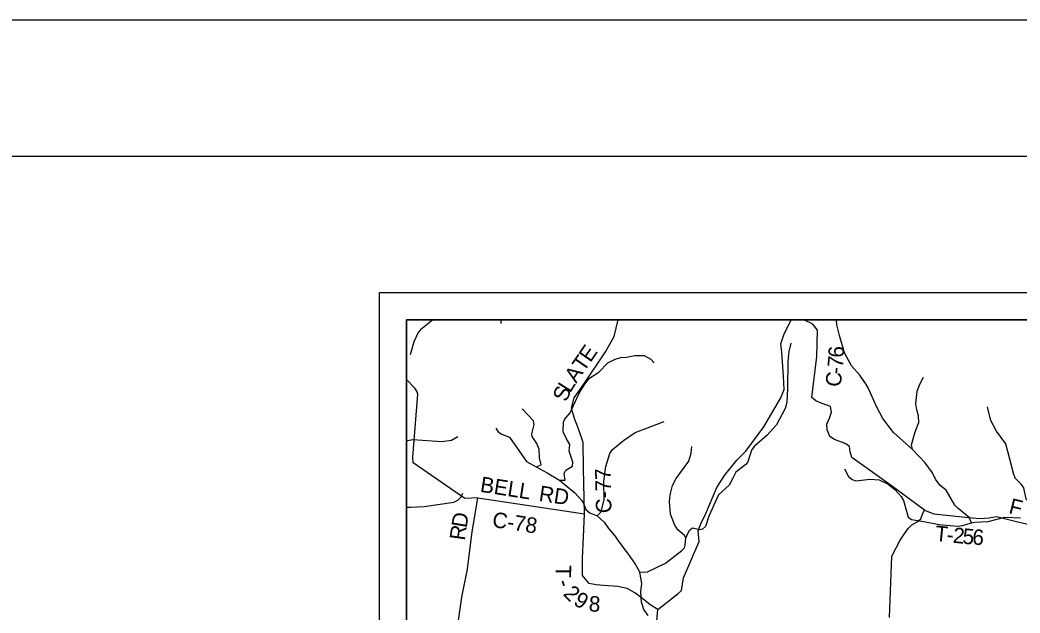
# Model space of a CAD drawing. Extents: x 0 to 34, y 0 to 22.
# Drawn here: x 22.598 to 26.267, y 19.825 to 22 of the extents above; entities that cross this region are included whole.
import ezdxf

# ---------------------------------------------------------------- set-up
doc = ezdxf.new("R2010")
doc.units = 0
for name, color, linetype in [('GM_X_County', 7, 'Continuous'), ('GM_X_County_Road', 7, 'Continuous'), ('GM_X_County_Road_Text', 7, 'Continuous'), ('GM_X_Minor_River', 7, 'Continuous'), ('GM_X_Township', 7, 'Continuous'), ('GM_X_Township_Road', 7, 'Continuous'), ('GM_X_Township_Road_Text', 7, 'Continuous'), ('SH_Border', 7, 'Continuous'), ('SH_Cut_Line', 7, 'Continuous'), ('SH_Data', 7, 'Continuous')]:
    doc.layers.add(name, color=color, linetype=linetype)

msp = doc.modelspace()

# ---------------------------------------------------------------- linework, layer by layer
at = {"layer": 'GM_X_County'}
msp.add_lwpolyline([(29.025, 20.9), (24.0167, 20.9), (24.0167, 14.5214)], dxfattribs=at)
at = {"layer": 'GM_X_County_Road'}
for points in [[(24.669, 20.1887), (24.6651, 20.3561), (24.6643, 20.4497), (24.6473, 20.5002), (24.6327, 20.5382), (24.621, 20.5761), (24.6315, 20.6146), (24.6688, 20.6673), (24.7466, 20.7829), (24.7779, 20.8392), (24.7928, 20.9)], [(25.7887, 19.8078), (25.7968, 20.0331), (25.8276, 20.0915), (25.8371, 20.1069), (25.8571, 20.1345), (25.8703, 20.1486), (25.8899, 20.1588), (25.9031, 20.1703), (25.9108, 20.191), (25.9168, 20.2026), (25.8038, 20.2848), (25.6505, 20.3956), (25.6434, 20.4163), (25.6412, 20.4357), (25.6282, 20.4459), (25.5868, 20.4609), (25.5693, 20.4724), (25.5596, 20.4965), (25.5586, 20.5175), (25.5682, 20.5393), (25.5752, 20.5611), (25.5711, 20.5822), (25.541, 20.5935), (25.5181, 20.6028), (25.5036, 20.6149), (25.522, 20.7657), (25.5235, 20.8619), (25.5063, 20.8847), (25.4744, 20.9)], [(24.1402, 19.4296), (24.1499, 19.4856), (24.1526, 19.5395), (24.1535, 19.5824), (24.1536, 19.6147), (24.16, 19.6322), (24.177, 19.6456), (24.1928, 19.6635), (24.194, 19.7022), (24.219, 19.8827), (24.2396, 19.9857), (24.2555, 20.1141), (24.2778, 20.2475), (24.2307, 20.2449), (24.0407, 20.3755), (24.0393, 20.3964), (24.0579, 20.6277), (24.0544, 20.6389), (24.0468, 20.649), (24.0167, 20.6817)], [(24.2778, 20.2475), (24.669, 20.1887)]]:
    msp.add_lwpolyline(points, dxfattribs=at)
at = {"layer": 'GM_X_Minor_River'}
for points in [[(24.1123, 20.9), (24.0677, 20.8641), (24.0591, 20.8543), (24.0429, 20.8193), (24.0302, 20.772)], [(24.3621, 20.9), (24.3624, 20.8869)], [(26.0887, 20.1557), (26.0799, 20.1757), (26.0395, 20.2083), (26.028, 20.221), (25.9956, 20.276), (25.9743, 20.2927), (25.9573, 20.3158), (25.9459, 20.3384), (25.9193, 20.3757), (25.872, 20.4248), (25.8022, 20.4869), (25.7633, 20.5377), (25.7416, 20.5795), (25.7092, 20.6534), (25.7015, 20.665), (25.6956, 20.6746), (25.6789, 20.6977), (25.6488, 20.7313), (25.6235, 20.7796), (25.6046, 20.8426), (25.5955, 20.8819), (25.5939, 20.9)], [(25.4256, 20.8143), (25.4186, 20.7836), (25.4149, 20.7472), (25.4134, 20.6481), (25.4117, 20.5968), (25.4048, 20.5749), (25.3741, 20.5154), (25.3399, 20.4777), (25.2917, 20.4356), (25.2823, 20.4221), (25.2682, 20.3794), (25.2612, 20.3697), (25.2246, 20.3414), (25.2139, 20.3196), (25.1998, 20.2933), (25.1608, 20.2582), (25.1251, 20.1806), (25.113, 20.1421), (25.1018, 20.132), (25.0919, 20.1303), (25.0655, 20.1361), (25.0535, 20.1257), (25.0453, 20.1129), (25.0412, 20.1)], [(24.5771, 20.3116), (24.5983, 20.312), (24.595, 20.3367), (24.6002, 20.3488), (24.6248, 20.3639), (24.6262, 20.378), (24.6129, 20.4181), (24.6152, 20.4428), (24.6016, 20.4658), (24.591, 20.4892), (24.5917, 20.5249), (24.5961, 20.5347), (24.617, 20.559), (24.6484, 20.6291), (24.6624, 20.6513), (24.6706, 20.6637), (24.6874, 20.6858), (24.722, 20.7083), (24.7549, 20.7419), (24.7817, 20.7559), (24.8031, 20.762), (24.8233, 20.7631), (24.8537, 20.769), (24.8883, 20.7699), (24.9131, 20.7554), (24.9246, 20.7423)], [(25.872, 20.4248), (25.8693, 20.4416), (25.8819, 20.4892), (25.8955, 20.5236), (25.8948, 20.5475), (25.888, 20.5697), (25.885, 20.5925), (25.8897, 20.6388), (25.8989, 20.6645), (25.9127, 20.6897)], [(26.3161, 20.1573), (26.3219, 20.1599), (26.3222, 20.1952), (26.3186, 20.209), (26.3102, 20.2232), (26.2897, 20.2429), (26.2805, 20.2834), (26.2728, 20.2957), (26.2508, 20.3185), (26.2446, 20.333), (26.2153, 20.4456), (26.1812, 20.4922), (26.1599, 20.5314), (26.148, 20.5817)], [(24.4914, 20.3614), (24.5106, 20.3683), (24.5042, 20.3938), (24.5025, 20.4258), (24.4949, 20.4468), (24.4776, 20.4722), (24.4762, 20.4817), (24.4849, 20.5165), (24.4821, 20.5299), (24.44, 20.5736)], [(24.7162, 20.1815), (24.7302, 20.1956), (24.7409, 20.2414), (24.7406, 20.3068), (24.7435, 20.3367), (24.7474, 20.3621), (24.7616, 20.4101), (24.7725, 20.424), (24.8122, 20.4579), (24.8553, 20.4867), (24.9612, 20.5274)], [(24.0167, 20.4556), (24.0201, 20.4576), (24.04, 20.4614), (24.1461, 20.4538), (24.1819, 20.4589), (24.2046, 20.4725)], [(24.3434, 20.5027), (24.3526, 20.4896), (24.3665, 20.4803), (24.394, 20.4699), (24.4565, 20.3806), (24.4914, 20.3614), (24.5328, 20.3394), (24.5771, 20.3116), (24.6336, 20.2661), (24.6588, 20.2383), (24.6655, 20.2272), (24.6738, 20.205), (24.6883, 20.1918), (24.7162, 20.1815), (24.7409, 20.1586), (24.7567, 20.1344), (24.7858, 20.1019)], [(25.0412, 20.1), (25.0357, 20.1096), (25.0118, 20.1298), (24.9989, 20.1498), (24.9844, 20.1869), (24.9807, 20.2341), (24.9835, 20.258), (24.9917, 20.2924), (25.0055, 20.3184), (25.0526, 20.3821), (25.0608, 20.4112), (25.0627, 20.4359)], [(25.6231, 20.3533), (25.6382, 20.3261), (25.6508, 20.3144), (25.6644, 20.3096), (25.7166, 20.3159), (25.7507, 20.313), (25.783, 20.2976), (25.8088, 20.277), (25.8311, 20.2516), (25.8392, 20.2377), (25.8567, 20.177), (25.8683, 20.1673), (25.9198, 20.1595), (25.9701, 20.1499), (26.0376, 20.143), (26.057, 20.1457), (26.0887, 20.1557), (26.1016, 20.1585), (26.1495, 20.1611), (26.2109, 20.1763), (26.2682, 20.1738)], [(24.0167, 20.2125), (24.0319, 20.2131), (24.0805, 20.2153), (24.1898, 20.2308), (24.204, 20.2389), (24.2167, 20.2512), (24.2231, 20.264)], [(24.9025, 19.8151), (24.8868, 19.8372), (24.8784, 19.8646), (24.8761, 19.9021), (24.8794, 19.9336), (24.8723, 19.9742), (24.8544, 20.0074), (24.8283, 20.0444), (24.819, 20.0562), (24.7858, 20.1019)], [(24.8723, 19.9742), (24.9003, 19.9754), (24.966, 20.0082), (25.0267, 20.0546), (25.0362, 20.0636), (25.039, 20.0738), (25.0412, 20.1)]]:
    msp.add_lwpolyline(points, dxfattribs=at)
at = {"layer": 'GM_X_Township'}
msp.add_lwpolyline([(29.025, 20.9), (24.0167, 20.9), (24.0167, 14.5214)], dxfattribs=at)
at = {"layer": 'GM_X_Township_Road'}
for points in [[(24.9383, 19.8374), (25.0132, 19.8969), (25.0246, 19.9069), (25.0329, 19.9542), (25.0899, 20.087), (25.0868, 20.1261), (25.0958, 20.1518), (25.1141, 20.1893), (25.1551, 20.2849), (25.1827, 20.3287), (25.2277, 20.3854), (25.2611, 20.4185), (25.3269, 20.5077), (25.3898, 20.6142), (25.4015, 20.6443), (25.3989, 20.6934), (25.393, 20.7813), (25.39, 20.8126), (25.4002, 20.8454), (25.4274, 20.9)], [(24.9383, 19.8374), (24.9097, 19.8543), (24.8766, 19.8818), (24.8545, 19.8991), (24.8259, 19.9145), (24.7914, 19.9219), (24.7394, 19.9261), (24.7121, 19.9282), (24.6867, 19.933), (24.6663, 19.9559), (24.6614, 19.9621), (24.6622, 20.0255), (24.6655, 20.1045), (24.669, 20.1887)], [(25.9168, 20.2026), (25.9513, 20.1885), (26.0777, 20.1753), (26.1194, 20.1712), (26.1539, 20.1735), (26.1802, 20.1789), (26.2632, 20.1579), (26.4051, 20.1268)], [(24.5884, 18.9379), (24.5995, 18.9709), (24.6243, 19.0083), (24.6408, 19.0479), (24.6701, 19.0868), (24.6941, 19.1245), (24.7086, 19.1679), (24.7239, 19.2036), (24.7509, 19.2532), (24.7708, 19.2882), (24.7858, 19.3126), (24.8095, 19.3461), (24.8355, 19.3702), (24.8604, 19.3958), (24.8792, 19.4198), (24.8892, 19.4457), (24.9027, 19.4671), (24.9166, 19.4884), (24.924, 19.5196), (24.9363, 19.7281), (24.9337, 19.7831), (24.9383, 19.8374)]]:
    msp.add_lwpolyline(points, dxfattribs=at)
at = {"layer": 'SH_Border'}
msp.add_lwpolyline([(2, 21.5), (33.5, 21.5), (33.5, 0.5), (2, 0.5)], close=True, dxfattribs=at)
at = {"layer": 'SH_Cut_Line'}
msp.add_lwpolyline([(0, 0), (34, 0), (34, 22), (0, 22)], close=True, dxfattribs=at)
at = {"layer": 'SH_Data'}
for points in [[(23.9167, 21), (30.9167, 21), (30.9167, 14), (23.9167, 14)], [(24.0167, 20.9), (30.8167, 20.9), (30.8167, 14.1), (24.0167, 14.1)]]:
    msp.add_lwpolyline(points, close=True, dxfattribs=at)

# ---------------------------------------------------------------- texts
at = {"layer": 'GM_X_County_Road_Text'}
for s, height, rotation, p in [('E', 0.0568, 55.531, (24.6909, 20.7412)), ('6', 0.0568, 87.2931, (25.6201, 20.7606)), ('T', 0.0568, 55.529, (24.6669, 20.7062)), ('7', 0.0568, 84.6729, (25.6167, 20.7229)), ('A', 0.0568, 55.5532, (24.6386, 20.665)), ('C', 0.0568, 83.5387, (25.6088, 20.6522)), ('-', 0.0568, 83.7955, (25.6141, 20.6988)), ('S', 0.0568, 68.6353, (24.6035, 20.5964)), ('L', 0.0568, 57.6544, (24.6162, 20.6295)), ('BELL', 0.05682, 351.1709, (24.284, 20.2697)), ('C-77', 0.05682, 91.3713, (24.7685, 20.1915)), ('RD', 0.05682, 351.5902, (24.4997, 20.2364)), ('D', 0.0568, 80.4185, (24.2366, 20.1348)), ('C-78', 0.05682, 351.3837, (24.3284, 20.1407)), ('R', 0.0568, 81.898, (24.2301, 20.089))]:
    msp.add_text(s, height=height, rotation=rotation, dxfattribs=at).set_placement(p)
at = {"layer": 'GM_X_Township_Road_Text'}
for s, rotation, p in [('F', 345.996, (26.2229, 20.1916)), ('T', 354.2173, (25.9533, 20.0894)), ('-', 354.2572, (25.9957, 20.0852)), ('2', 354.3632, (26.019, 20.0828)), ('5', 354.8114, (26.0543, 20.0793)), ('6', 356.1873, (26.0906, 20.076)), ('T', 269.3786, (24.5638, 20.0012)), ('-', 288.7107, (24.5666, 19.9382)), ('2', 314.4888, (24.5885, 19.8925)), ('9', 329.062, (24.6254, 19.8578)), ('8', 356.6817, (24.6837, 19.8311))]:
    msp.add_text(s, height=0.0568, rotation=rotation, dxfattribs=at).set_placement(p)

doc.saveas('drawing.dxf')
